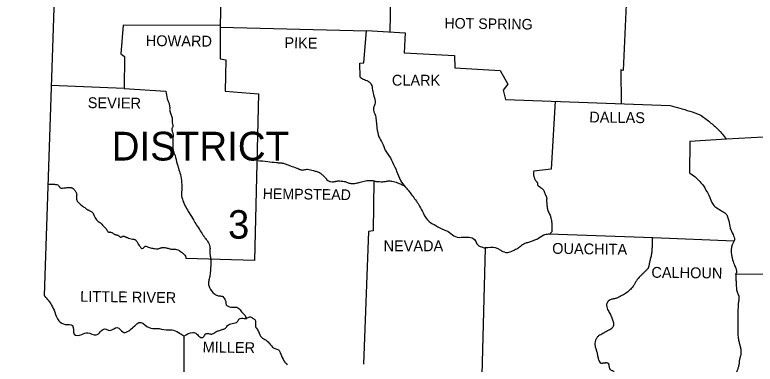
# Model space of a CAD drawing. Extents: x 1373878 to 1386598, y 1168333 to 1170533.
# Drawn here: x 1376295.6 to 1376588.9, y 1169816.7 to 1169955.3 of the extents above; entities that cross this region are included whole.
import ezdxf

# ---------------------------------------------------------------- set-up
doc = ezdxf.new("R2010")
doc.units = 0
doc.layers.add('1', color=7, linetype='Continuous')
doc.layers.add('Default', color=7, linetype='Continuous')

msp = doc.modelspace()

# ---------------------------------------------------------------- linework, layer by layer
at = {"layer": '1'}
msp.add_line((1376445.29, 1170011.31), (1376444.13, 1169948.51), dxfattribs=at)
for points in [[(1376295.59, 1170281.4), (1376316.29, 1170115.21), (1376307.29, 1169843.91)], [(1376406.23, 1170053.77), (1376406.09, 1170012.81), (1376401.09, 1170012.71), (1376401.49, 1170009.71), (1376396.69, 1170009.81), (1376396.59, 1170007.61), (1376391.89, 1170007.61), (1376391.99, 1170006.01), (1376384.99, 1170005.81), (1376384.89, 1169999.71), (1376378.09, 1170000.31), (1376376.99, 1169951.11), (1376338.49, 1169951.21), (1376337.59, 1169939.81), (1376338.99, 1169938.81), (1376338.89, 1169926.01), (1376310.06, 1169927.28)], [(1376537.79, 1169959.41), (1376536.59, 1169933.21), (1376535.69, 1169933.51), (1376535.79, 1169920.03)], [(1376376.99, 1169950.42), (1376434.88, 1169948.9)], [(1376432.49, 1169930.61), (1376432.29, 1169936.11), (1376433.89, 1169936.21), (1376434.89, 1169949.11), (1376450.29, 1169948.11), (1376449.89, 1169940.21), (1376469.79, 1169939.11), (1376469.89, 1169934.31), (1376487.89, 1169933.21), (1376490.99, 1169927.81), (1376489.09, 1169925.41), (1376489.99, 1169921.71), (1376555.19, 1169919.31)], [(1376592.19, 1169906.81), (1376577.57, 1169905.91)], [(1376481.89, 1169862.81), (1376480.59, 1169812.41), (1376467.09, 1169813.31), (1376466.99, 1169809.61), (1376449.2, 1169810.66)], [(1376362.59, 1169827.81), (1376362.79, 1169746.92), (1376729.29, 1169746.32)]]:
    msp.add_lwpolyline(points, dxfattribs=at)
for points in [[(1376432.49, 1169930.61), (1376434.09, 1169929.61), (1376435.99, 1169928.71), (1376436.99, 1169927.21), (1376437.39, 1169924.91), (1376438.09, 1169922.41), (1376438.29, 1169919.81), (1376437.69, 1169918.41), (1376438.49, 1169915.21), (1376438.79, 1169913.01), (1376439.09, 1169910.41), (1376439.89, 1169906.91), (1376441.19, 1169904.51), (1376442.39, 1169901.61), (1376444.39, 1169898.51), (1376446.09, 1169895.11), (1376446.89, 1169893.31), (1376448.39, 1169889.61), (1376450.29, 1169887.11), (1376453.29, 1169883.31), (1376455.99, 1169879.41), (1376457.49, 1169876.51), (1376459.79, 1169873.31), (1376462.39, 1169871.71), (1376465.69, 1169870.01), (1376467.79, 1169869.01), (1376470.19, 1169867.31), (1376473.29, 1169867.11), (1376475.59, 1169867.11), (1376477.69, 1169866.21), (1376478.69, 1169864.41), (1376480.49, 1169863.21), (1376481.89, 1169862.81)], [(1376555.19, 1169919.31), (1376562.99, 1169917.11), (1376566.99, 1169915.61), (1376570.99, 1169912.71), (1376574.29, 1169909.81), (1376577.57, 1169905.91)], [(1376307.29, 1169843.91), (1376310.19, 1169840.11), (1376311.39, 1169837.41), (1376313.09, 1169833.91), (1376315.59, 1169832.51), (1376318.49, 1169832.01), (1376319.09, 1169828.61), (1376322.09, 1169828.51), (1376324.49, 1169829.21), (1376327.79, 1169828.31), (1376331.29, 1169830.71), (1376333.29, 1169830.11), (1376336.19, 1169831.31), (1376338.39, 1169829.51), (1376342.19, 1169831.11), (1376345.59, 1169833.31), (1376348.79, 1169831.21), (1376351.89, 1169830.91), (1376355.59, 1169830.41), (1376358.49, 1169830.21), (1376361.09, 1169828.91), (1376362.4, 1169828.01), (1376362.59, 1169827.81)]]:
    msp.add_spline(points, degree=3, dxfattribs=at)
at = {"layer": 'Default'}
for points in [[(1376376.99, 1169951.11), (1376376.99, 1169937.81), (1376379.19, 1169937.41), (1376378.99, 1169925.01), (1376392.19, 1169924.01), (1376390.59, 1169857.91), (1376363.39, 1169858.61)], [(1376338.89, 1169926.01), (1376355.49, 1169925.01)], [(1376509.66, 1169920.99), (1376508.09, 1169894.11), (1376501.19, 1169893.31)], [(1376577.63, 1169905.91), (1376562.99, 1169905.01), (1376562.89, 1169892.51)], [(1376437.79, 1169889.46), (1376437.59, 1169869.61), (1376435.79, 1169869.41), (1376433.79, 1169816.71)], [(1376507.09, 1169868.41), (1376548.49, 1169866.91), (1376580.61, 1169865.66)], [(1376581.19, 1169852.41), (1376626.39, 1169852.51)]]:
    msp.add_lwpolyline(points, dxfattribs=at)
for points in [[(1376355.49, 1169925.01), (1376355.99, 1169922.01), (1376356.18, 1169921.35), (1376356.44, 1169920.71), (1376356.69, 1169920.07), (1376356.89, 1169919.41), (1376356.95, 1169918.92), (1376356.96, 1169918.41), (1376356.95, 1169917.91), (1376356.99, 1169917.41), (1376357.19, 1169916.66), (1376357.47, 1169915.92), (1376357.73, 1169915.17), (1376357.89, 1169914.41), (1376357.89, 1169913.31), (1376357.95, 1169912.76), (1376358.05, 1169912.21), (1376358.14, 1169911.66), (1376358.19, 1169911.11), (1376358.14, 1169910.81), (1376358, 1169910.51), (1376357.86, 1169910.21), (1376357.79, 1169909.91), (1376357.88, 1169909.32), (1376358.06, 1169908.72), (1376358.23, 1169908.12), (1376358.29, 1169907.51), (1376358.19, 1169905.71), (1376358.19, 1169904.21), (1376358.29, 1169901.71), (1376358.43, 1169901.15), (1376358.66, 1169900.6), (1376358.9, 1169900.06), (1376359.09, 1169899.51), (1376359.89, 1169896.21), (1376360.39, 1169894.51), (1376361.19, 1169891.91), (1376361.69, 1169888.71), (1376361.79, 1169886.31), (1376361.76, 1169885.76), (1376361.68, 1169885.21), (1376361.61, 1169884.66), (1376361.59, 1169884.11), (1376362.19, 1169881.61), (1376363.29, 1169879.11), (1376364.69, 1169876.71), (1376366.39, 1169874.01), (1376367.59, 1169871.91), (1376369.09, 1169869.61), (1376370.29, 1169867.71), (1376370.72, 1169867.1), (1376371.18, 1169866.52), (1376371.65, 1169865.93), (1376372.09, 1169865.31), (1376372.89, 1169863.31), (1376372.94, 1169862.61), (1376372.91, 1169861.91), (1376372.87, 1169861.21), (1376372.89, 1169860.51), (1376372.99, 1169859.86), (1376373.12, 1169859.22), (1376373.24, 1169858.57), (1376373.29, 1169857.91), (1376373.19, 1169855.01), (1376372.99, 1169852.41), (1376372.85, 1169851.51), (1376372.63, 1169850.61), (1376372.42, 1169849.71), (1376372.29, 1169848.81), (1376372.79, 1169847.11), (1376374.69, 1169844.61), (1376375.89, 1169843.91), (1376376.41, 1169843.79), (1376376.95, 1169843.77), (1376377.49, 1169843.72), (1376377.99, 1169843.51), (1376378.58, 1169842.87), (1376378.99, 1169842.11), (1376379.14, 1169841.59), (1376379.19, 1169841.02), (1376379.28, 1169840.47), (1376379.4, 1169840.23), (1376379.59, 1169840.01), (1376380.61, 1169839.52), (1376381.69, 1169839.31), (1376381.99, 1169839.28), (1376382.29, 1169839.29), (1376382.92, 1169839.36), (1376383.51, 1169839.36), (1376383.99, 1169839.11), (1376385.09, 1169837.91), (1376386.59, 1169836.31), (1376387.33, 1169834.91)], [(1376391.55, 1169897.51), (1376395.79, 1169897.11), (1376399.29, 1169896.71), (1376400.65, 1169896.6), (1376401.32, 1169896.54), (1376401.66, 1169896.48), (1376401.99, 1169896.41), (1376402.71, 1169896.2), (1376403.41, 1169895.95), (1376404.79, 1169895.41), (1376407.29, 1169894.51), (1376407.7, 1169894.35), (1376408.09, 1169894.16), (1376408.48, 1169893.97), (1376408.89, 1169893.81), (1376409.56, 1169893.74), (1376410.24, 1169893.86), (1376410.92, 1169894), (1376411.59, 1169894.01), (1376412.75, 1169893.79), (1376413.89, 1169893.51), (1376415.23, 1169893.16), (1376415.87, 1169892.93), (1376416.19, 1169892.78), (1376416.49, 1169892.61), (1376417.49, 1169891.81), (1376418.39, 1169890.91), (1376418.68, 1169890.59), (1376418.95, 1169890.25), (1376419.59, 1169889.61), (1376420.15, 1169889.31), (1376420.73, 1169889.16), (1376421.89, 1169889.11), (1376422.37, 1169889.17), (1376422.84, 1169889.27), (1376423.32, 1169889.37), (1376423.79, 1169889.41), (1376426.09, 1169889.21), (1376426.75, 1169889.04), (1376427.4, 1169888.79), (1376428.04, 1169888.56), (1376428.69, 1169888.41), (1376429.22, 1169888.37), (1376429.75, 1169888.37), (1376430.79, 1169888.51), (1376432.49, 1169888.91), (1376434.49, 1169889.41), (1376435.74, 1169889.61), (1376436.37, 1169889.63), (1376436.99, 1169889.61), (1376437.47, 1169889.54), (1376437.94, 1169889.42), (1376438.41, 1169889.3), (1376438.89, 1169889.21), (1376440.14, 1169889.13), (1376441.39, 1169889.11), (1376442.12, 1169889.17), (1376442.84, 1169889.29), (1376443.57, 1169889.39), (1376443.93, 1169889.42), (1376444.29, 1169889.41), (1376445.03, 1169889.32), (1376447.21, 1169888.69), (1376448.63, 1169888.08), (1376450.02, 1169887.46)], [(1376501.19, 1169893.31), (1376501.08, 1169892.37), (1376501.12, 1169891.88), (1376501.19, 1169891.41), (1376501.31, 1169890.95), (1376501.47, 1169890.49), (1376501.67, 1169890.05), (1376501.89, 1169889.61), (1376502.05, 1169889.4), (1376502.24, 1169889.2), (1376502.43, 1169889.02), (1376502.59, 1169888.81), (1376502.69, 1169888.5), (1376502.71, 1169888.14), (1376502.74, 1169887.8), (1376502.8, 1169887.64), (1376502.89, 1169887.51), (1376503.1, 1169887.34), (1376503.34, 1169887.2), (1376503.57, 1169887.07), (1376503.79, 1169886.91), (1376503.97, 1169886.78), (1376504.15, 1169886.64), (1376504.51, 1169886.37), (1376504.84, 1169886.07), (1376504.98, 1169885.9), (1376505.09, 1169885.71), (1376505.29, 1169885.29), (1376505.46, 1169884.87), (1376505.62, 1169884.44), (1376505.79, 1169884.01), (1376506.06, 1169883.47), (1376506.19, 1169883.2), (1376506.25, 1169883.06), (1376506.29, 1169882.91), (1376506.34, 1169882.57), (1376506.33, 1169882.21), (1376506.3, 1169881.86), (1376506.29, 1169881.51), (1376506.34, 1169880.81), (1376506.39, 1169880.11), (1376506.47, 1169879.26), (1376506.52, 1169878.84), (1376506.59, 1169878.41), (1376506.82, 1169877.64), (1376507.16, 1169876.9), (1376507.51, 1169876.17), (1376507.79, 1169875.41), (1376508.09, 1169874.21), (1376508.29, 1169873.21), (1376508.39, 1169871.51), (1376508.41, 1169871.01), (1376508.42, 1169870.51), (1376508.41, 1169870.01), (1376508.41, 1169869.76), (1376508.39, 1169869.51), (1376508.31, 1169869.23), (1376508.11, 1169868.92), (1376507.57, 1169868.4)], [(1376562.89, 1169892.51), (1376565.19, 1169891.01), (1376567.09, 1169889.01), (1376568.49, 1169887.51), (1376569.39, 1169885.81), (1376570.59, 1169883.81), (1376572.29, 1169880.01), (1376573.79, 1169878.71), (1376575.89, 1169877.41), (1376577.19, 1169876.51), (1376578.49, 1169873.61), (1376579.09, 1169870.71), (1376580.19, 1169868.11), (1376580.69, 1169866.11), (1376579.79, 1169864.11), (1376579.59, 1169860.11), (1376580.19, 1169857.41), (1376580.99, 1169855.41), (1376581.49, 1169853.11), (1376581.19, 1169852.41)], [(1376308.76, 1169888.05), (1376309.77, 1169888.14), (1376310.8, 1169888.12), (1376311.77, 1169888.01), (1376312.59, 1169887.81), (1376312.95, 1169887.53), (1376313.29, 1169887.08), (1376313.65, 1169886.67), (1376314.09, 1169886.51), (1376314.99, 1169886.61), (1376316.59, 1169886.81), (1376316.97, 1169886.84), (1376317.34, 1169886.84), (1376317.72, 1169886.8), (1376318.09, 1169886.71), (1376318.42, 1169886.56), (1376318.7, 1169886.35), (1376318.95, 1169886.1), (1376319.19, 1169885.81), (1376319.5, 1169885.43), (1376319.76, 1169885.05), (1376319.96, 1169884.65), (1376320.09, 1169884.21), (1376320.11, 1169883.84), (1376320.06, 1169883.46), (1376320, 1169883.09), (1376319.99, 1169882.71), (1376320.09, 1169882.11), (1376320.21, 1169881.75), (1376320.36, 1169881.41), (1376320.79, 1169880.81), (1376321.99, 1169879.81), (1376323.29, 1169878.81), (1376324.49, 1169878.01), (1376324.75, 1169877.86), (1376325.03, 1169877.72), (1376325.61, 1169877.46), (1376326.12, 1169877.15), (1376326.49, 1169876.71), (1376326.69, 1169876.31), (1376327.49, 1169874.71), (1376327.94, 1169874.02), (1376328.2, 1169873.71), (1376328.49, 1169873.41), (1376328.78, 1169873.19), (1376329.1, 1169873.01), (1376329.41, 1169872.84), (1376329.69, 1169872.61), (1376330.99, 1169871.21), (1376331.59, 1169870.61), (1376331.86, 1169870.28), (1376332.08, 1169869.9), (1376332.31, 1169869.54), (1376332.44, 1169869.37), (1376332.59, 1169869.21), (1376332.84, 1169869.11), (1376333.13, 1169869.13), (1376333.42, 1169869.16), (1376333.69, 1169869.11), (1376334.07, 1169868.9), (1376334.44, 1169868.65), (1376334.81, 1169868.41), (1376335.19, 1169868.21), (1376335.46, 1169868.13), (1376335.74, 1169868.06), (1376336.03, 1169867.99), (1376336.29, 1169867.91), (1376336.6, 1169867.74), (1376336.89, 1169867.51), (1376337.18, 1169867.28), (1376337.49, 1169867.11), (1376337.79, 1169867.14), (1376338.09, 1169867.32), (1376338.4, 1169867.49), (1376338.69, 1169867.51), (1376339.07, 1169867.37), (1376339.44, 1169867.21), (1376339.82, 1169867.05), (1376340.19, 1169866.91), (1376342.19, 1169866.31), (1376342.47, 1169866.27), (1376342.76, 1169866.26), (1376343.17, 1169866.18), (1376343.23, 1169866.15), (1376343.29, 1169866.11), (1376343.71, 1169865.7), (1376344.02, 1169865.22), (1376344.29, 1169864.7), (1376344.43, 1169864.45), (1376344.59, 1169864.21), (1376345.21, 1169863.39), (1376345.54, 1169862.99), (1376345.89, 1169862.61), (1376346.07, 1169862.53), (1376346.25, 1169862.59), (1376346.65, 1169862.94), (1376347.06, 1169863.35), (1376347.28, 1169863.49), (1376347.49, 1169863.51), (1376348.23, 1169863.32), (1376348.98, 1169863.05), (1376349.73, 1169862.78), (1376350.49, 1169862.61), (1376351.45, 1169862.51), (1376352.39, 1169862.51), (1376352.82, 1169862.61), (1376353.24, 1169862.77), (1376353.66, 1169862.93), (1376354.09, 1169863.01), (1376355.39, 1169862.91), (1376356, 1169862.78), (1376356.59, 1169862.61), (1376357.19, 1169862.44), (1376357.79, 1169862.31), (1376358.16, 1169862.29), (1376358.54, 1169862.31), (1376358.92, 1169862.34), (1376359.29, 1169862.31), (1376360.89, 1169861.71), (1376362.39, 1169860.51), (1376363.39, 1169859.21), (1376363.39, 1169858.61)], [(1376502.59, 1169866.31), (1376505.19, 1169868.01), (1376507.09, 1169868.41)], [(1376502.59, 1169866.31), (1376501.87, 1169866.02), (1376500.59, 1169865.51), (1376499.09, 1169865.01), (1376497.69, 1169864.61), (1376495.89, 1169863.41), (1376494.49, 1169862.41), (1376492.59, 1169861.51), (1376490.79, 1169860.91), (1376488.59, 1169861.61), (1376487.39, 1169862.31), (1376486.09, 1169862.81), (1376481.89, 1169862.81)], [(1376548.16, 1169866.93), (1376548.09, 1169863.82), (1376548.02, 1169862.26), (1376547.97, 1169861.49), (1376547.89, 1169860.71), (1376547.59, 1169859.15), (1376547.19, 1169857.61), (1376546.93, 1169856.19), (1376546.76, 1169855.49), (1376546.64, 1169855.15), (1376546.57, 1169854.98), (1376546.49, 1169854.81), (1376546.19, 1169854.35), (1376545.81, 1169853.96), (1376544.99, 1169853.21), (1376544.19, 1169852.42), (1376543.39, 1169851.61), (1376541.89, 1169849.81), (1376541.55, 1169849.28), (1376541.25, 1169848.71), (1376540.94, 1169848.15), (1376540.59, 1169847.61), (1376539.29, 1169846.21), (1376537.59, 1169844.81), (1376535.89, 1169843.81), (1376533.99, 1169842.91), (1376533.48, 1169842.75), (1376532.95, 1169842.65), (1376532.42, 1169842.56), (1376531.89, 1169842.41), (1376531.06, 1169841.99), (1376530.7, 1169841.69), (1376530.54, 1169841.51), (1376530.39, 1169841.31), (1376530.13, 1169840.73), (1376530.04, 1169840.11), (1376530.29, 1169838.91), (1376530.7, 1169838.06), (1376531.15, 1169837.22), (1376531.59, 1169836.38), (1376531.99, 1169835.51), (1376532.59, 1169833.91), (1376532.73, 1169833.45), (1376532.81, 1169832.97), (1376532.84, 1169832.49), (1376532.79, 1169832.01), (1376532.09, 1169830.91), (1376530.49, 1169830.01), (1376528.59, 1169828.91), (1376526.89, 1169827.91), (1376526.49, 1169827.59), (1376526.16, 1169827.18), (1376525.9, 1169826.72), (1376525.69, 1169826.21), (1376525.42, 1169825.06), (1376525.49, 1169823.91), (1376525.68, 1169823.24), (1376525.89, 1169822.56), (1376526.11, 1169821.89), (1376526.29, 1169821.21), (1376526.44, 1169820.42), (1376526.59, 1169819.61), (1376526.98, 1169818.2), (1376527.33, 1169817.58), (1376527.58, 1169817.32), (1376527.73, 1169817.21), (1376527.89, 1169817.11), (1376528.14, 1169817.06), (1376528.39, 1169817.1), (1376528.64, 1169817.17), (1376528.89, 1169817.21), (1376529.12, 1169817.23), (1376529.34, 1169817.26), (1376529.8, 1169817.33), (1376530.25, 1169817.31), (1376530.47, 1169817.24), (1376530.58, 1169817.19), (1376530.69, 1169817.11), (1376530.84, 1169816.88), (1376530.89, 1169816.61), (1376530.99, 1169816.11), (1376531.39, 1169814.81), (1376531.69, 1169814.48), (1376532.14, 1169814.26), (1376532.59, 1169814.04), (1376532.89, 1169813.71), (1376532.96, 1169813.47), (1376533, 1169813.22), (1376533.03, 1169812.96), (1376533.09, 1169812.71), (1376533.47, 1169811.74), (1376533.99, 1169810.81), (1376534.31, 1169810.41), (1376534.66, 1169810.05), (1376535.49, 1169809.51), (1376536.59, 1169809.11), (1376538.89, 1169808.41), (1376540.09, 1169808.11), (1376540.26, 1169808.03), (1376540.58, 1169807.55), (1376540.73, 1169806.58), (1376540.89, 1169805.66), (1376541.08, 1169805.35), (1376541.39, 1169805.21), (1376542.19, 1169805.22), (1376542.99, 1169805.31), (1376544.19, 1169805.51), (1376545.2, 1169805.47), (1376545.7, 1169805.3), (1376545.95, 1169805.17), (1376546.19, 1169805.01), (1376546.73, 1169804.45), (1376547.09, 1169803.81), (1376547.33, 1169803.32), (1376547.54, 1169802.82), (1376547.75, 1169802.31), (1376547.99, 1169801.81), (1376548.52, 1169801.05), (1376548.8, 1169800.75)], [(1376581.19, 1169852.41), (1376581.27, 1169850.86), (1376581.36, 1169849.31), (1376581.59, 1169846.21), (1376581.77, 1169845.45), (1376582.08, 1169844.71), (1376582.37, 1169843.97), (1376582.46, 1169843.6), (1376582.49, 1169843.21), (1376582.45, 1169842.42), (1376582.35, 1169841.62), (1376582.26, 1169840.82), (1376582.19, 1169840.01), (1376582.09, 1169836.91), (1376582.09, 1169834.11), (1376582.09, 1169831.41), (1376582.09, 1169828.61), (1376582.29, 1169826.61), (1376582.44, 1169825.88), (1376582.63, 1169825.16), (1376582.82, 1169824.44), (1376582.99, 1169823.71), (1376583.24, 1169822.36), (1376583.3, 1169821.69), (1376583.29, 1169821.01), (1376583.19, 1169820.36), (1376583.02, 1169819.71), (1376582.84, 1169819.07), (1376582.69, 1169818.41), (1376582.62, 1169817.82), (1376582.57, 1169817.21), (1376582.5, 1169816.61), (1376582.39, 1169816.01), (1376582.21, 1169815.41), (1376582, 1169814.81), (1376581.78, 1169814.22), (1376581.59, 1169813.61), (1376580.89, 1169810.91), (1376580.09, 1169807.41), (1376579.78, 1169806.25), (1376579.6, 1169805.68), (1376579.39, 1169805.11), (1376579.09, 1169804.49), (1376578.72, 1169803.9), (1376578.34, 1169803.31), (1376577.99, 1169802.71), (1376577.75, 1169802.17), (1376577.54, 1169801.62), (1376577.33, 1169801.06), (1376577.09, 1169800.51), (1376576.78, 1169800.14), (1376576.37, 1169799.84), (1376575.96, 1169799.53), (1376575.8, 1169799.34), (1376575.69, 1169799.11), (1376575.47, 1169797.92), (1376575.49, 1169796.71), (1376575.56, 1169796.16), (1376575.65, 1169795.61), (1376575.74, 1169795.06), (1376575.79, 1169794.51), (1376575.77, 1169794.02), (1376575.7, 1169793.52), (1376575.62, 1169793.01), (1376575.59, 1169792.51), (1376575.77, 1169791.55), (1376576.29, 1169790.61), (1376576.63, 1169790.21), (1376576.99, 1169789.82), (1376577.72, 1169789.32)], [(1376362.59, 1169827.81), (1376366.09, 1169829.31), (1376367.59, 1169828.81), (1376368.89, 1169827.51), (1376370.39, 1169827.51), (1376371.19, 1169828.71), (1376372.69, 1169828.81), (1376373.89, 1169828.71), (1376375.19, 1169829.51), (1376376.29, 1169830.01), (1376377.79, 1169830.51), (1376378.89, 1169830.91), (1376379.89, 1169832.01), (1376381.69, 1169832.91), (1376383.79, 1169833.61), (1376384.39, 1169834.61), (1376385.39, 1169835.01), (1376387.39, 1169834.91), (1376388.69, 1169835.51), (1376389.79, 1169835.01), (1376390.79, 1169834.31), (1376390.99, 1169831.71), (1376391.79, 1169830.31), (1376392.99, 1169827.81), (1376394.69, 1169826.51), (1376396.29, 1169825.21), (1376396.89, 1169824.41), (1376398.59, 1169822.91), (1376400.09, 1169822.41), (1376400.79, 1169821.31), (1376401.89, 1169818.71), (1376403.49, 1169816.41)]]:
    msp.add_spline(points, degree=3, dxfattribs=at)

# ---------------------------------------------------------------- texts
for s, height, rotation, p in [('HOT SPRING', 4.2, 359.2216, (1376465.79, 1169949.91)), ('HOWARD', 4.301, 359.5145, (1376347.49, 1169942.91)), ('PIKE', 4.299, 359.0452, (1376402.39, 1169942.11)), ('SEVIER', 4.301, 359.4271, (1376324.49, 1169918.31)), ('DALLAS', 4.299, 359.2462, (1376523.19, 1169912.61)), ('HEMPSTEAD', 4.199, 359.1885, (1376393.79, 1169882.31)), ('OUACHITA', 4.301, 359.2043, (1376508.49, 1169860.51)), ('CALHOUN', 4.301, 359.3634, (1376547.79, 1169851.01)), ('LITTLE RIVER', 4.3006, 359.1697, (1376321.49, 1169841.51)), ('MILLER', 4.299, 359.132, (1376369.99, 1169821.41))]:
    msp.add_text(s, height=height, rotation=rotation, dxfattribs=at).set_placement(p)
for s, height, p in [('CLARK', 4.3, (1376444.99, 1169927.21)), ('DISTRICT', 11.4, (1376333.99, 1169897.51)), ('3', 11.3, (1376380.09, 1169866.51)), ('NEVADA', 4.3, (1376441.69, 1169861.51))]:
    msp.add_text(s, height=height, dxfattribs=at).set_placement(p)

doc.saveas('drawing.dxf')
